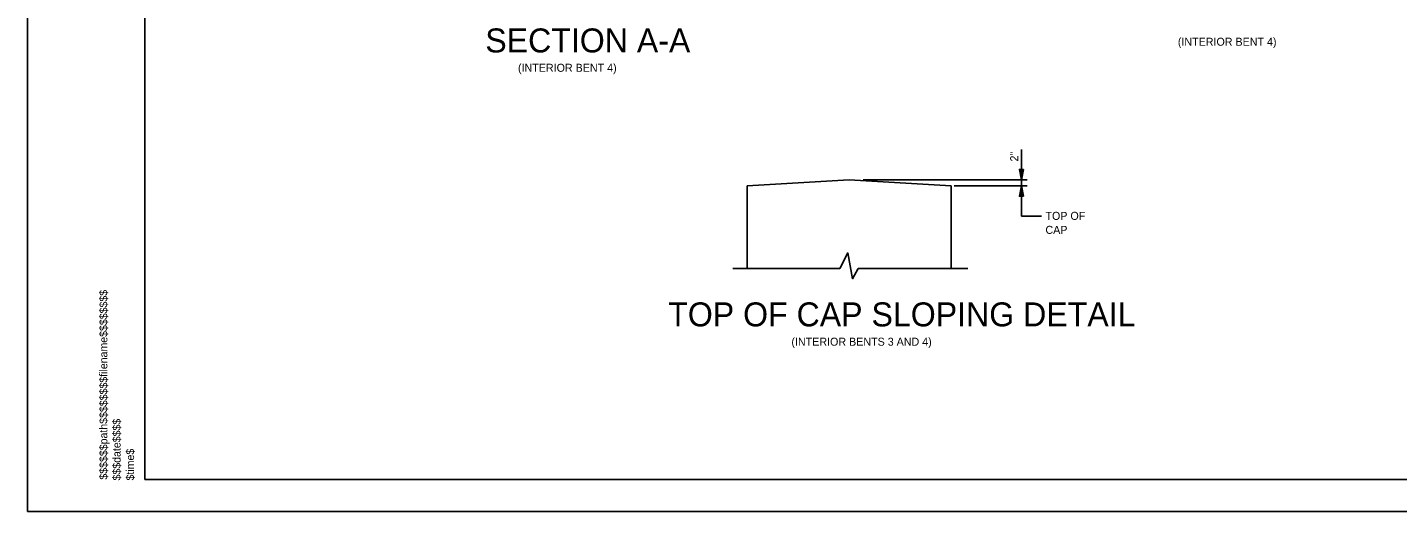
# Model space of a CAD drawing. Extents: x 1970675.2 to 1970711.3, y 796145.2 to 796167.2.
# Drawn here: x 1970675.24 to 1970696.64, y 796145.25 to 796152.81 of the extents above; entities that cross this region are included whole.
import ezdxf

# ---------------------------------------------------------------- set-up
doc = ezdxf.new("R2010")
doc.units = 0
for name, color, linetype in [('BR_AUTO DIMENSION', 7, 'Continuous'), ('BR_BORDER LINES', 7, 'Continuous'), ('BR_CONCRETE', 7, 'Continuous'), ('BR_TEXT', 7, 'Continuous'), ('Default', 7, 'Continuous'), ('Level 31', 7, 'Continuous'), ('RD_SHT_ID', 7, 'Continuous')]:
    doc.layers.add(name, color=color, linetype=linetype)

msp = doc.modelspace()

# ---------------------------------------------------------------- linework, layer by layer
at = {"layer": 'BR_AUTO DIMENSION'}
for p, q in [((1970690.766, 796150.904), (1970690.766, 796149.863)), ((1970688.296, 796150.431), (1970690.858, 796150.431)), ((1970689.718, 796150.337), (1970690.858, 796150.337)), ((1970691.079, 796149.863), (1970690.766, 796149.863))]:
    msp.add_line(p, q, dxfattribs=at)
for points in [[(1970690.797, 796150.593), (1970690.766, 796150.431), (1970690.734, 796150.593)], [(1970690.797, 796150.174), (1970690.766, 796150.337), (1970690.734, 796150.174)]]:
    msp.add_lwpolyline(points, close=True, dxfattribs=at)
at = {"layer": 'BR_BORDER LINES'}
for q in [(1970677.07, 796166.746), (1970710.736, 796145.746)]:
    msp.add_line((1970677.07, 796145.746), q, dxfattribs=at)
at = {"layer": 'BR_CONCRETE'}
for p, q in [((1970686.482, 796150.337), (1970688.076, 796150.431)), ((1970686.482, 796150.337), (1970686.482, 796149.048)), ((1970689.67, 796150.337), (1970688.076, 796150.431)), ((1970689.67, 796150.337), (1970689.67, 796149.048))]:
    msp.add_line(p, q, dxfattribs=at)
at = {"layer": 'Default'}
for p, q in [((1970686.26, 796149.048), (1970687.93, 796149.048)), ((1970688.218, 796149.048), (1970689.93, 796149.048))]:
    msp.add_line(p, q, dxfattribs=at)
msp.add_lwpolyline([(1970688.218, 796149.048), (1970688.129, 796148.886), (1970688.054, 796149.288), (1970687.93, 796149.048)], dxfattribs=at)
at = {"layer": 'Level 31'}
msp.add_lwpolyline([(1970675.236, 796145.246), (1970711.236, 796145.246), (1970711.236, 796167.246), (1970675.236, 796167.246)], close=True, dxfattribs=at)

# ---------------------------------------------------------------- texts
at = {"layer": 'BR_AUTO DIMENSION'}
msp.add_text('2"', height=0.125, rotation=90, dxfattribs=at).set_placement((1970690.716, 796150.718))
for s, p in [('TOP OF', (1970691.142, 796149.806)), ('CAP', (1970691.142, 796149.587))]:
    msp.add_text(s, height=0.125, dxfattribs=at).set_placement(p)
at = {"layer": 'BR_TEXT'}
for s, p in [('SECTION A-A', (1970682.39, 796152.422)), ('TOP OF CAP SLOPING DETAIL', (1970685.248, 796148.141))]:
    msp.add_text(s, height=0.375, dxfattribs=at).set_placement(p)
for s, p in [('(INTERIOR BENT 4)', (1970693.21, 796152.527)), ('(INTERIOR BENT 4)', (1970682.901, 796152.12)), ('(INTERIOR BENTS 3 AND 4)', (1970687.173, 796147.839))]:
    msp.add_text(s, height=0.125, rotation=360, dxfattribs=at).set_placement(p)
at = {"layer": 'RD_SHT_ID'}
for s, height, p in [('$$$$$$path$$$$$$$$filename$$$$$$$$', 0.12347, (1970676.486, 796145.746)), ('$$$date$$$$', 0.12347, (1970676.692, 796145.733)), ('$time$', 0.1235, (1970676.903, 796145.733))]:
    msp.add_text(s, height=height, rotation=90, dxfattribs=at).set_placement(p)

doc.saveas('drawing.dxf')
